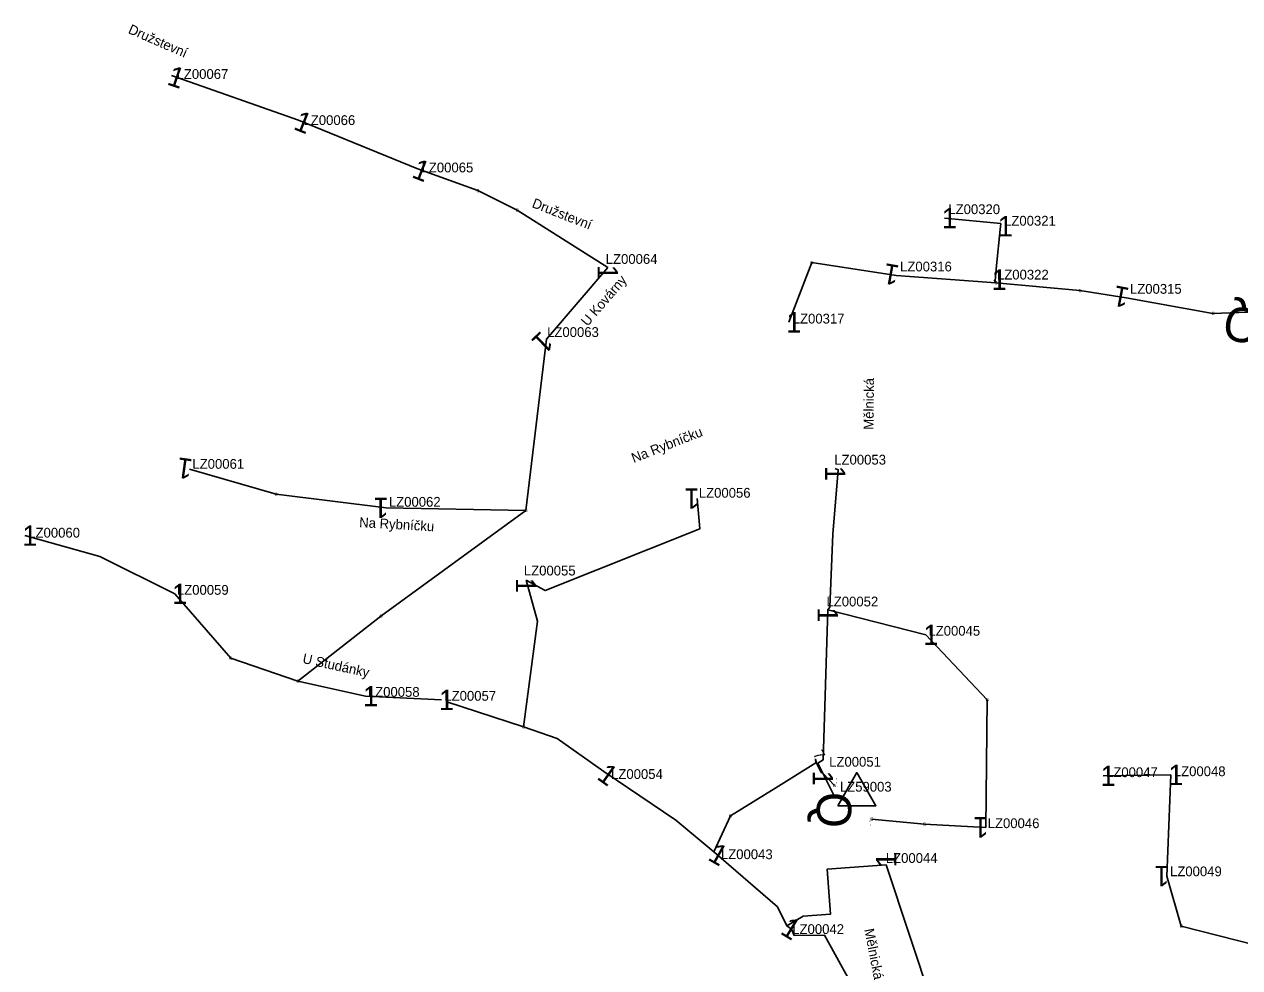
# Model space of a CAD drawing. Extents: x -736540 to -735418, y -1033000 to -1031598.
# Drawn here: x -736321.7 to -736011.7, y -1032109 to -1031868.4 of the extents above; entities that cross this region are included whole.
import ezdxf

# ---------------------------------------------------------------- set-up
doc = ezdxf.new("R2010")
doc.units = 0
for name, color, linetype in [('ftf_2010', 7, 'Continuous'), ('ftf_2050', 7, 'Continuous'), ('ftf_2080', 7, 'Continuous'), ('ftf_2240', 7, 'Continuous'), ('ftf_3010', 7, 'Continuous'), ('ftf_3010_ftf_3010_gtda_3015_gtda_3015_1', 7, 'Continuous'), ('ftf_3130', 7, 'Continuous'), ('ftf_3170', 7, 'Continuous'), ('ftf_3240', 7, 'Continuous'), ('ftf_3260', 7, 'Continuous'), ('ftf_3260_ftf_3260_gtda_3265_gtda_3265_1', 7, 'Continuous'), ('ftf_nu', 7, 'Continuous')]:
    doc.layers.add(name, color=color, linetype=linetype)

msp = doc.modelspace()

# ---------------------------------------------------------------- linework, layer by layer
at = {"layer": 'ftf_2010'}
for points in [[(-736086.98, -1031917.85), (-736072.62, -1031919.24), (-736072.76, -1031920.79)], [(-736073.84, -1031934.37), (-736074.04, -1031933.82), (-736073.68, -1031929.98), (-736072.76, -1031920.79)], [(-736074.3, -1031933.57), (-736073.84, -1031934.37)], [(-736114.84, -1031981.68), (-736114.08, -1031982.02), (-736115.47, -1031998.44), (-736116.17, -1032017.08), (-736116.74, -1032017.75)], [(-736193.7, -1032010.23), (-736188.84, -1032012.84), (-736149.39, -1031997.14), (-736150.09, -1031989.39)], [(-736321.57, -1031998.83), (-736302.42, -1032004.14), (-736283.32, -1032013.66)], [(-736193.7, -1032010.23), (-736190.82, -1032020.61), (-736194.37, -1032047.59), (-736185.8, -1032050.53), (-736173.87, -1032059)], [(-736116.74, -1032017.75), (-736117.94, -1032056.04), (-736119.28, -1032056.89), (-736117.97, -1032059.41)], [(-736141.56, -1032070.31), (-736129.95, -1032063.12), (-736119.76, -1032056.81), (-736119.9, -1032055.72)], [(-736119.9, -1032055.72), (-736119.61, -1032056.89), (-736118.4, -1032059.21), (-736117.97, -1032059.41)], [(-736173.87, -1032059), (-736155.52, -1032071.43), (-736145.76, -1032079.46)], [(-736046.5, -1032060.06), (-736029.23, -1032059.86)], [(-736030.22, -1032085.66), (-736029.23, -1032059.86)], [(-736145.76, -1032079.46), (-736129.57, -1032093.5), (-736127.21, -1032098.34)], [(-736101.83, -1032082.79), (-736116.85, -1032083.87), (-736116.08, -1032095.41), (-736123, -1032095.88), (-736127.21, -1032098.34)], [(-736084.14, -1032136.1), (-736101.83, -1032082.79)], [(-736127.21, -1032098.34), (-736125.97, -1032099.2), (-736125.31, -1032100.78), (-736117.57, -1032100.74), (-736109.87, -1032114.77), (-736107.59, -1032126.1)]]:
    msp.add_lwpolyline(points, dxfattribs=at)
at = {"layer": 'ftf_2050'}
for points in [[(-736284.11, -1031881.47), (-736251.71, -1031892.92)], [(-736251.71, -1031892.92), (-736221.59, -1031905.18)], [(-736221.59, -1031905.18), (-736206.01, -1031910.86), (-736195.95, -1031915.84), (-736172.85, -1031930.42)], [(-736188.52, -1031948.75), (-736172.85, -1031930.42)], [(-736126.67, -1031944.44), (-736120.81, -1031929.21), (-736099.29, -1031932.46)], [(-736099.29, -1031932.46), (-736073.84, -1031934.37), (-736052.41, -1031936.35), (-736040.65, -1031938.16)], [(-736040.65, -1031938.16), (-736018.49, -1031942.16), (-735992.06, -1031941.13)], [(-736188.52, -1031948.75), (-736193.74, -1031992.39)], [(-736279.52, -1031981.88), (-736257.47, -1031988.3), (-736229.39, -1031991.75)], [(-736193.74, -1031992.39), (-736230.72, -1032019.37), (-736251.9, -1032035.95)], [(-736229.39, -1031991.75), (-736193.74, -1031992.39)], [(-736283.32, -1032013.66), (-736269.03, -1032030.1), (-736251.9, -1032035.95), (-736234.64, -1032039.77)], [(-736234.64, -1032039.77), (-736215.29, -1032040.73)], [(-736213.9, -1032041.18), (-736194.37, -1032047.59)]]:
    msp.add_lwpolyline(points, dxfattribs=at)
at = {"layer": 'ftf_2080'}
for points in [[(-736116.74, -1032017.75), (-736091.71, -1032024.13)], [(-736091.71, -1032024.13), (-736076.08, -1032040.71), (-736076.38, -1032073.23)], [(-736117.97, -1032059.41), (-736115.15, -1032065)], [(-736117.97, -1032059.41), (-736115.05, -1032062.56)], [(-736145.76, -1032079.46), (-736141.56, -1032070.31)], [(-736105.55, -1032071.11), (-736092.05, -1032072.41), (-736076.38, -1032073.23)], [(-736030.22, -1032085.66), (-736026.59, -1032098.41), (-736007.51, -1032103.26), (-735994.86, -1032107.74)]]:
    msp.add_lwpolyline(points, dxfattribs=at)
at = {"layer": 'ftf_2240'}
msp.add_lwpolyline([(-736114.19, -1032067.7), (-736104.46, -1032067.7), (-736109.33, -1032059.27)], close=True, dxfattribs=at)

# ---------------------------------------------------------------- texts
at = {"layer": 'ftf_3010'}
for rotation, p in [(341.3914, (-736285.55, -1031883.73)), (338.1458, (-736253.28, -1031895.1)), (338.7407, (-736223.14, -1031907.37)), (270, (-736175.45, -1031929.77)), (170.0364, (-736098.21, -1031930.01)), (169.2388, (-736039.53, -1031935.73)), (223.7641, (-736189.85, -1031946.42)), (172.1547, (-736278.52, -1031979.39)), (270, (-736117.44, -1031981.03)), (180, (-736149.44, -1031986.79)), (180, (-736228.74, -1031989.15)), (270, (-736196.3, -1032009.59)), (270, (-736119.34, -1032017.11)), (324.5146, (-736175.91, -1032060.74)), (270, (-736120.57, -1032058.77)), (180, (-736075.73, -1032070.63)), (330.5165, (-736147.6, -1032081.4)), (90, (-736099.23, -1032083.44)), (180, (-736029.58, -1032083.06)), (328.7171, (-736129.12, -1032100.22))]:
    msp.add_text('1', height=5.2, rotation=rotation, dxfattribs=at).set_placement(p)
for p in [(-736087.63, -1031920.45), (-736073.39, -1031922.54), (-736074.95, -1031936.17), (-736127.32, -1031947.04), (-736322.22, -1032001.43), (-736283.97, -1032016.26), (-736092.36, -1032026.73), (-736235.29, -1032042.37), (-736215.93, -1032043.33), (-736047.15, -1032062.66), (-736029.88, -1032062.46)]:
    msp.add_text('1', height=5.2, dxfattribs=at).set_placement(p)
at = {"layer": 'ftf_3010_ftf_3010_gtda_3015_gtda_3015_1'}
for s, p in [('LZ00067', (-736282.85, -1031882.37)), ('LZ00066', (-736250.47, -1031894.13)), ('LZ00065', (-736220.36, -1031906.21)), ('LZ00320', (-736085.98, -1031916.85)), ('LZ00321', (-736071.76, -1031919.79)), ('LZ00316', (-736098.29, -1031931.46)), ('LZ00322', (-736073.57, -1031933.53)), ('LZ00315', (-736039.65, -1031937.16)), ('LZ00317', (-736125.67, -1031944.75)), ('LZ00060', (-736320.68, -1031999.34)), ('LZ00059', (-736282.76, -1032013.92)), ('LZ00052', (-736117.07, -1032016.89)), ('LZ00045', (-736091.06, -1032024.36)), ('LZ00058', (-736234.05, -1032039.94)), ('LZ00057', (-736214.54, -1032040.94)), ('LZ00054', (-736172.01, -1032060.89)), ('LZ00047', (-736045.75, -1032060.43)), ('LZ00048', (-736028.46, -1032060.18)), ('LZ00043', (-736143.99, -1032081.34))]:
    msp.add_text(s, height=2.5, dxfattribs=at).set_placement(p)
for s, p in [('LZ00064', (-736173.37, -1031929.54)), ('LZ00063', (-736188.33, -1031948.18)), ('LZ00053', (-736115.08, -1031980.72)), ('LZ00061', (-736278.81, -1031981.79)), ('LZ00056', (-736149.63, -1031989.17)), ('LZ00062', (-736228.69, -1031991.47)), ('LZ00055', (-736194.26, -1032009)), ('LZ00051', (-736116.38, -1032057.76)), ('LZ00046', (-736075.94, -1032073.43)), ('LZ00044', (-736101.93, -1032082.3)), ('LZ00049', (-736029.43, -1032085.7)), ('LZ00042', (-736125.79, -1032100.43))]:
    msp.add_text(s, height=2.5, rotation=0, dxfattribs=at).set_placement(p)
at = {"layer": 'ftf_3130'}
for rotation, p in [(180, (-736114.18, -1032060.74)), (6.801, (-736106.15, -1032072.79))]:
    msp.add_text(':', height=1.6, rotation=rotation, dxfattribs=at).set_placement(p)
at = {"layer": 'ftf_3170'}
msp.add_text('7', height=2.7, rotation=300.9184, dxfattribs=at).set_placement((-736120.6, -1032054.56))
at = {"layer": 'ftf_3240'}
for p in [(-736206.41, -1031911.26), (-736196.35, -1031916.24), (-736121.21, -1031929.61), (-736074.24, -1031934.77), (-736052.81, -1031936.75), (-736018.89, -1031942.56), (-736257.87, -1031988.7), (-736194.14, -1031992.79), (-736231.12, -1032019.77), (-736269.43, -1032030.5), (-736252.3, -1032036.35), (-736076.48, -1032041.11), (-736194.77, -1032047.99), (-736115.45, -1032062.96), (-736141.96, -1032070.71), (-736105.95, -1032071.51), (-736092.45, -1032072.81), (-736026.99, -1032098.81)]:
    msp.add_text('G', height=0.8, dxfattribs=at).set_placement(p)
at = {"layer": 'ftf_3260'}
for rotation, p in [(169.8199, (-736005.85, -1031941.57)), (270, (-736119.55, -1032064.22))]:
    msp.add_text('Q', height=8.8, rotation=rotation, dxfattribs=at).set_placement(p)
at = {"layer": 'ftf_3260_ftf_3260_gtda_3265_gtda_3265_1'}
msp.add_text('LZ59003', height=2.5, rotation=0, dxfattribs=at).set_placement((-736113.64, -1032064.12))
at = {"layer": 'ftf_nu'}
for s, rotation, p in [('Družstevní', 336.4082, (-736295.38, -1031870.63)), ('Družstevní', 338.5766, (-736192.39, -1031915.02)), ('U Kovárny', 49.2294, (-736178.02, -1031945.62)), ('Mělnická', 89.3282, (-736105.08, -1031971.84)), ('Na Rybníčku', 21.3919, (-736166.23, -1031980.33)), ('Na Rybníčku', 356.7801, (-736236.31, -1031996.66)), ('U Studánky', 347.573, (-736250.87, -1032031.3)), ('Mělnická', 281.1659, (-736107.45, -1032099.28))]:
    msp.add_text(s, height=2.5, rotation=rotation, dxfattribs=at).set_placement(p)

doc.saveas('drawing.dxf')
